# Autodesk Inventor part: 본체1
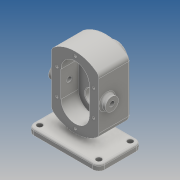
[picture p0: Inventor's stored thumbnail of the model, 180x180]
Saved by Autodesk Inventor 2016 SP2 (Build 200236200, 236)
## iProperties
Created: 2019-03
Part Number: 본체1
Material: Generic
Document SubType Name: Modeling
Designer: EZ
Density: 1 g/cm^3
Appearance: Default
Author: EZ
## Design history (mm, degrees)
sketch "스케치1"
  geometry: L1 (60, -36.5)-(-60, -36.5); L2 (-60, -36.5)-(-60, 36.5); L3 (-60, 36.5)-(60, 36.5); L4 (60, 36.5)-(60, -36.5); L5 (60, -36.5)-(-60, 36.5); L6 (-60, -36.5)-(60, 36.5); 1 further point
  constraints: 12 end point, 2 midpoint, 2 parallel, 1 horizontal, 1 perpendicular
  dimensions: "d0" = 120 distance of L2.end L3.end; "d1" = 73 distance of L1.end L2.end
extrude "돌출1" new body sketch "스케치1" distance "d2" = 10; taper "d3" = 0 deg
fillet "모깎기1" dims "d4" = 10
sketch "스케치2" dims "d14" = 138
  geometry: L1 (-50, 36.5)-(50, 36.5) reference; L2 (60, 26.5)-(60, -26.5) reference; L3 (50, -36.5)-(-50, -36.5) reference; L4 (-60, -26.5)-(-60, 26.5) reference; A1 r 10 centre (-50, 26.5) between (-50, 36.5) and (-60, 26.5) reference; A2 r 10 centre (50, 26.5) between (60, 26.5) and (50, 36.5) reference; A3 r 10 centre (50, -26.5) between (50, -36.5) and (60, -26.5) reference; A4 r 10 centre (-50, -26.5) between (-60, -26.5) and (-50, -36.5) reference; 5 further points
  constraints: 4 coincident
hole "구멍1" sketch "스케치2" at (-50, 26.5), (-50, -26.5), (50, -26.5), (50, 26.5) diameter "d5" = 9; stored, may be unused: countersink angle "d9" = 90 deg, drill point angle "d11" = 118 deg; dims "d6" = 6, "d7" = 4, "d8" = 2, "d10" = 8, "d14" = 138
sketch "스케치3"
  geometry: L1 (36.5, 0)-(-36.5, 0) reference; L2 (-36.5, 0)-(-36.5, 10) reference; L3 (-36.5, 10)-(36.5, 10) reference; L4 (36.5, 10)-(36.5, 0) reference; L5 (-16.5, 78)-(36.5, 78); L6 (-16.5, 78)-(-16.5, 138); L7 (-16.5, 138)-(36.5, 138); L8 (36.5, 138)-(36.5, 78)
  constraints: 8 end point, 3 perpendicular, 1 horizontal
  dimensions: "d13" = 78 distance between parallel lines of L5 L1; "d14" = 138 distance between parallel lines of L1 L7; "d15" = 53 distance between parallel lines of L4 L6; "d16" = 53 distance between parallel lines of L6 L8
extrude "돌출2" join sketch "스케치3" stored distance "d18" = 80; taper "d19" = 0 deg
sketch "스케치4"
  geometry: L1 (80, 0)-(80, -120) reference; L2 (0, 0)-(80, 0) reference; L3 (0, 0)-(0, -120) reference; L4 (0, -120)-(80, -120) reference; A1 r 60 centre (40, -60) between (0, -104.721) and (80, -104.721); A2 r 60 centre (40, -60) between (80, -15.279) and (0, -15.279); A3 r 60 centre (40, -60) between (80, -104.721) and (80, -15.279); 2 further points
  constraints: 6 point on circle, 4 point on line, 3 centre point, 2 tangent, 1 midpoint, 1 vertical alignment
  dimensions: "d20" = 120 diameter of A1
extrude "돌출3" cut sketch "스케치4" distance "d21" = 80; taper "d22" = 0 deg
sketch "스케치5"
  geometry: L1 (-50, 36.5)-(50, 36.5) reference; L2 (60, 26.5)-(60, -26.5) reference; L3 (50, -36.5)-(-50, -36.5) reference; L4 (-60, -26.5)-(-60, 26.5) reference; L5 (0, 36.5)-(0, -36.5); L6 (-6, 36.5)-(-6, -6.5); L7 (-6, -6.5)-(6, -6.5); L8 (6, -6.5)-(6, 36.5); C1 r 4.5 at (50, -26.5) reference; C2 r 4.5 at (-50, 26.5) reference; C3 r 4.5 at (-50, -26.5) reference; C4 r 4.5 at (50, 26.5) reference; A1 r 10 centre (-50, 26.5) between (-50, 36.5) and (-60, 26.5) reference; A2 r 10 centre (50, 26.5) between (60, 26.5) and (50, 36.5) reference; A3 r 10 centre (50, -26.5) between (50, -36.5) and (60, -26.5) reference; A4 r 10 centre (-50, -26.5) between (-60, -26.5) and (-50, -36.5) reference
  constraints: 8 end point, 2 midpoint, 2 perpendicular, 2 point on line, 1 vertical
  dimensions: "d27" = 43 distance of L6.start L6.end; "d28" = 6 distance between parallel lines of L5 L6; "d29" = 12 distance between parallel lines of L6 L8
extrude "돌출4" join sketch "스케치5" stored distance "d30" = 80; taper "d31" = 0 deg
sketch "스케치6"
  geometry: L1 (40, 44.721)-(40, -44.721) reference; L2 (-40, 44.721)-(-40, -44.721) reference; L3 (0, 22)-(0, -22); L4 (24, 22)-(24, -22); L5 (-24, -22)-(-24, 22); A1 r 60 centre (0, 0) between (-40, -44.721) and (40, -44.721) reference; A2 r 60 centre (0, 0) between (40, 44.721) and (-40, 44.721) reference; A3 r 24 centre (0, 22) between (24, 22) and (-24, 22); A4 r 24 centre (0, -22) between (-24, -22) and (24, -22); 2 further points
  constraints: 8 end point, 4 point on circle, 4 tangent, 2 centre point, 1 midpoint, 1 parallel, 1 vertical
  dimensions: "d32" = 78 distance of point (0, -78) point (0, 0); "d34" = 22 distance of A1.centre L3.start; "d35" = 44 distance of L3.end L3.start; "d39" = 24 radius of A3
extrude "돌출5" cut sketch "스케치6" distance "d40" = 29; taper "d41" = 0 deg
sketch "스케치7"
  geometry: L1 (24, 22)-(24, -22) reference; L2 (-24, -22)-(-24, 22) reference; L3 (40, 44.721)-(40, -44.721) reference; L4 (-40, 44.721)-(-40, -44.721) reference; L5 (0, 22)-(0, -22); L6 (31, 22)-(31, -22); L7 (-31, -22)-(-31, 22); A1 r 24 centre (0, 22) between (24, 22) and (-24, 22) reference; A2 r 24 centre (0, -22) between (-24, -22) and (24, -22) reference; A3 r 60 centre (0, 0) between (-40, -44.721) and (40, -44.721) reference; A4 r 60 centre (0, 0) between (40, 44.721) and (-40, 44.721) reference; A5 r 31 centre (0, 22) between (31, 22) and (-31, 22); A6 r 31 centre (0, -22) between (-31, -22) and (31, -22); 8 further points
  constraints: 8 end point, 6 point on circle, 4 coincident, 4 tangent, 2 centre point, 1 midpoint, 1 parallel, 1 vertical
  dimensions: "d42" = 31 radius of A5
hole "구멍2" sketch "스케치7" at (0, 53), (-31, 22), (31, 22), (31, -22), (-31, -22), (0, -53) diameter "d43" = 4.134; stored, may be unused: countersink angle "d47" = 90 deg, drill point angle "d49" = 118 deg; dims "d44" = 10, "d45" = 4, "d46" = 2, "d48" = 12
sketch "스케치8"
  geometry: L1 (-33.279, 36.5)-(-33.279, -16.5) reference; L2 (-122.721, -16.5)-(-33.279, -16.5) reference; L3 (-122.721, -16.5)-(-122.721, 36.5) reference; L4 (-122.721, 36.5)-(-33.279, 36.5) reference; L5 (0, -26.5)-(0, 26.5) reference; C1 r 11 at (-78, -2.5); 1 further point
  constraints: 1 centre point
  dimensions: "d51" = 22 diameter of C1; "d52" = 78 distance from line of L5 C1.centre; "d53" = 14 distance from line of L2 C1.centre
extrude "돌출6" join sketch "스케치8" distance "d54" = 8; taper "d55" = 0 deg
hole "구멍3" diameter "d59" = 8.376; stored, may be unused: countersink angle "d63" = 90 deg, drill point angle "d65" = 118 deg; dims "d57" = 10, "d58" = 10, "d60" = 20, "d61" = 4, "d62" = 2, "d64" = 27.3
fillet "모깎기4" dims "d66" = 3
sketch "스케치10"
  geometry: L1 (-40, -44.721)-(-40, 44.721) reference; L2 (40, 44.721)-(40, -44.721) reference; L3 (6, -62.354)-(6, -65) reference; L4 (9, -68)-(60, -68) reference; L5 (60, -68)-(60, -78) reference; L6 (60, -78)-(-60, -78) reference; L7 (-60, -78)-(-60, -68) reference; L8 (-60, -68)-(-9, -68) reference; L9 (-6, -65)-(-6, -62.354) reference; L10 (-24, 22)-(-24, -22) reference; L11 (24, -22)-(24, 22) reference; C1 r 12.5 at (0, -22); A1 r 3 centre (-9, -62.354) between (-6, -62.354) and (-8.571, -59.385) reference; A2 r 60 centre (0, 0) between (-40, -44.721) and (-8.571, -59.385) reference; A3 r 60 centre (0, 0) between (40, 44.721) and (-40, 44.721) reference; A4 r 60 centre (0, 0) between (8.571, -59.385) and (40, -44.721) reference; A5 r 3 centre (9, -62.354) between (8.571, -59.385) and (6, -62.354) reference; A6 r 3 centre (9, -65) between (6, -65) and (9, -68) reference; A7 r 3 centre (-9, -65) between (-9, -68) and (-6, -65) reference; A8 r 24 centre (0, 22) between (24, 22) and (-24, 22) reference; A9 r 24 centre (0, -22) between (-24, -22) and (24, -22) reference; 1 further point
  constraints: 1 centre point, 1 coincident
  dimensions: "d72" = 25 diameter of C1
extrude "돌출7" cut sketch "스케치10" distance "d73" = 15; taper "d74" = 0 deg
sketch "스케치11"
  geometry: L1 (36.5, 122.721)-(36.5, 33.279) reference; L2 (36.5, 119)-(53.5, 119); L3 (53.5, 100)-(36.5, 100); L4 (-16.5, 56)-(-16.5, 100) reference; L5 (-16.5, 78)-(36.5, 78); L6 (-26.5, 0)-(26.5, 0) reference; L7 (53.5, 119)-(53.5, 100); 2 further points
  constraints: 8 end point, 2 horizontal, 2 midpoint, 2 point on line, 1 perpendicular, 1 vertical
  dimensions: "d76" = 78 distance between parallel lines of L6 L5; "d77" = 22 distance between parallel lines of L5 L3; "d79" = 17 distance of L2.start L2.end; "d80" = 38 diameter of L2 L3
revolve "회전1" sketch "스케치11" stored, may be unused: angle "d81" = 90 deg
fillet "모깎기6" dims "d82" = 3
sketch "스케치12"
  geometry: L1 (-16.5, 32)-(12.5, 32) reference; L2 (12.5, 32)-(12.5, 43.5) reference; L3 (12.5, 43.5)-(27.5, 43.5) reference; L4 (27.5, 43.5)-(27.5, 68.5) reference; L5 (27.5, 68.5)-(12.5, 68.5) reference; L6 (12.5, 68.5)-(12.5, 124) reference; L7 (12.5, 124)-(-16.5, 124) reference; L8 (-16.5, 124)-(-16.5, 128.933) reference; L9 (-16.5, 128.933)-(-4.5, 128.933) reference; L10 (-4.5, 128.933)-(-3.258, 131) reference; L11 (-3.258, 131)-(-4.5, 133.067) reference; L12 (-4.5, 133.067)-(-16.5, 133.067) reference; L13 (-16.5, 133.067)-(-16.5, 138) reference; L14 (-16.5, 138)-(36.5, 138) reference; L15 (36.5, 138)-(36.5, 122) reference; L16 (39.5, 119)-(53.5, 119) reference; L17 (53.5, 119)-(53.5, 81) reference; L18 (53.5, 81)-(39.5, 81) reference; L19 (36.5, 78)-(36.5, 0) reference; L20 (36.5, 0)-(-36.5, 0) reference; L21 (-36.5, 0)-(-36.5, 10) reference; L22 (-36.5, 10)-(-6.5, 10) reference; L23 (-6.5, 10)-(-6.5, 18) reference; L24 (-6.5, 18)-(-16.5, 18) reference; L25 (-16.5, 18)-(-16.5, 22.933) reference; L26 (-16.5, 22.933)-(-4.5, 22.933) reference; L27 (-4.5, 22.933)-(-3.258, 25) reference; L28 (-3.258, 25)-(-4.5, 27.067) reference; L29 (-4.5, 27.067)-(-16.5, 27.067) reference; L30 (-16.5, 27.067)-(-16.5, 32) reference; L31 (12.5, 78)-(36.5, 78); L32 (12.5, 100)-(53.5, 100); L33 (12.5, 112.5)-(27.5, 112.5); L34 (27.5, 112.5)-(27.5, 108.5); L35 (27.5, 108.5)-(46.2, 108.5); L36 (46.2, 108.5)-(46.2, 113.7); L37 (46.5, 114)-(53.5, 114); L38 (12.5, 112.5)-(12.5, 100); L39 (53.5, 114)-(53.5, 100); A1 r 3 centre (39.5, 122) between (36.5, 122) and (39.5, 119) reference; A2 r 3 centre (39.5, 78) between (39.5, 81) and (36.5, 78) reference; A3 r 0.3 centre (46.5, 113.7) between (46.5, 114) and (46.2, 113.7); 2 further points
  constraints: 18 end point, 7 point on line, 4 perpendicular, 2 collinear, 2 horizontal, 2 point on circle, 2 tangent, 1 centre point, 1 midpoint, 1 vertical
  dimensions: "d83" = 78 distance between parallel lines of L20 L31; "d84" = 22 distance between parallel lines of L31 L32; "d85" = 7.3 distance of point (46.2, 114) L37.end; "d86" = 15 distance of L33.start L33.end; "d87" = 25 diameter of L33 L32; "d88" = 17 diameter of L35 L32; "d89" = 28 diameter of L37 L32; "d90" = 0.3 radius of A3
revolve "회전2" sketch "스케치12" stored, may be unused: angle "d91" = 90 deg
fillet "모깎기7" dims "d92" = 3
fillet "모깎기8" dims "d93" = 3
fillet "모깎기9" dims "d94" = 3
fillet "모깎기10" dims "d95" = 10
chamfer "모따기1" distance "d96" = 1; stored, may be unused: second distance "d97" = 2, angle "d98" = 30 deg
node "솔리드1"
mirror "대칭1"
mirror "대칭2"
node "투영된 루프1"
node "투영된 루프2"
node "투영된 루프3"
node "투영된 루프4"
node "투영된 루프5"
node "투영된 루프6"
node "절단 모서리 투영1"
node "절단 모서리 투영3"
node "절단 모서리 투영4"
